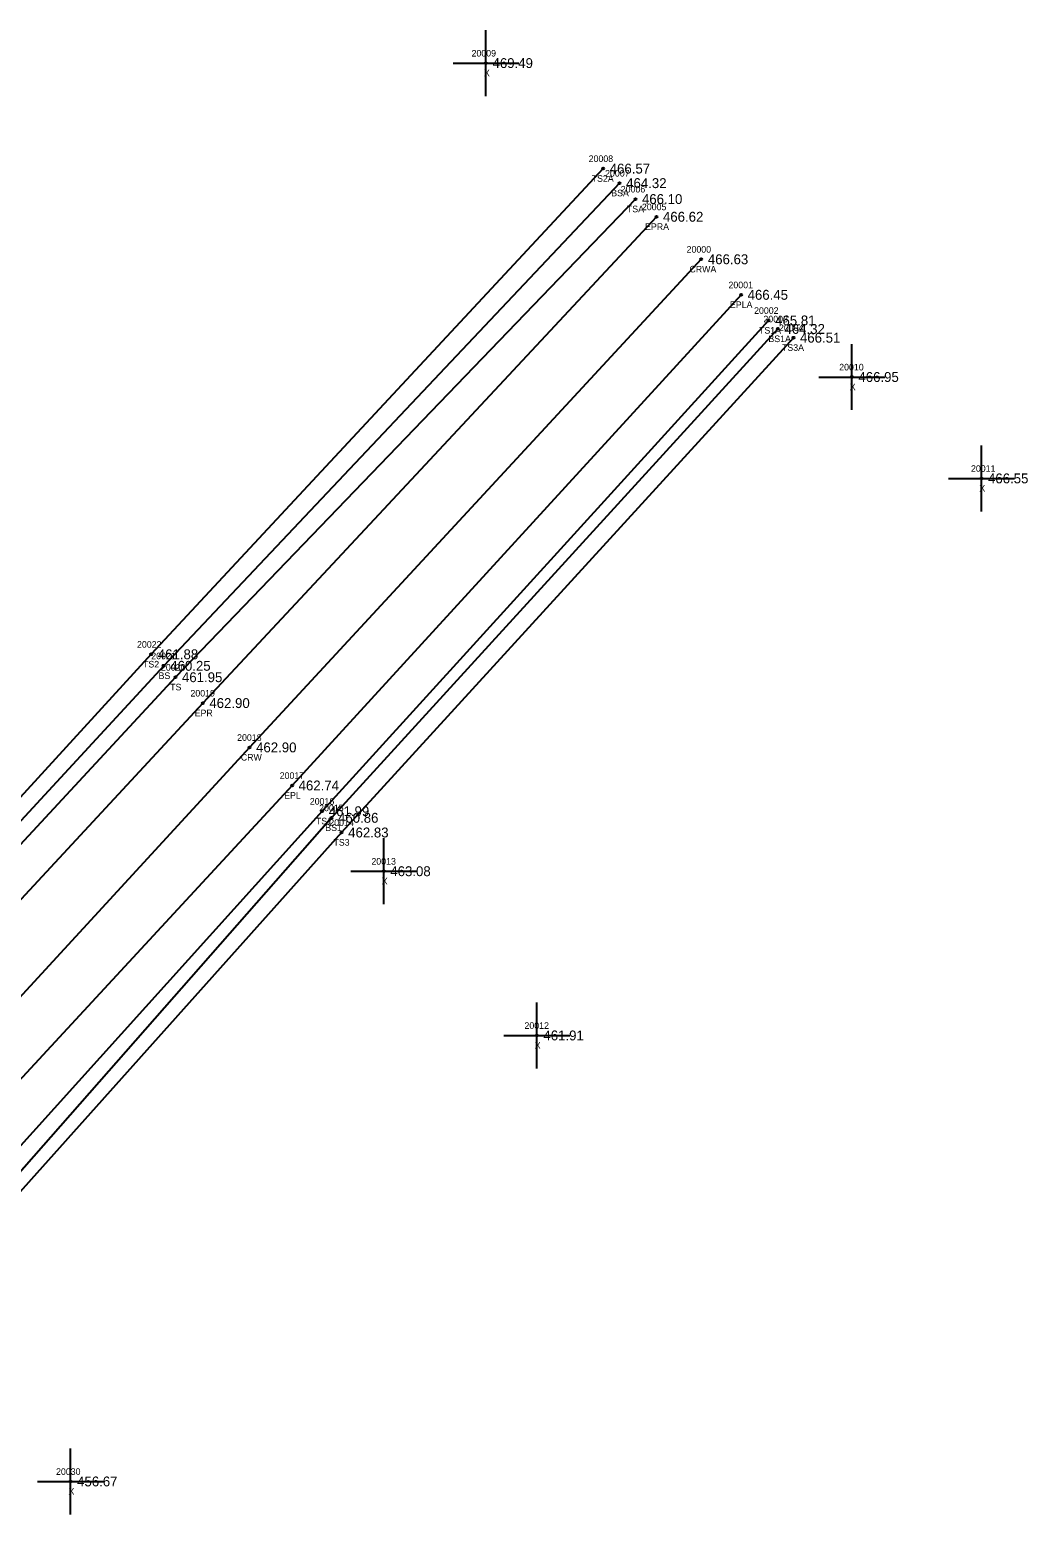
# Model space of a CAD drawing. Extents: x 1763022 to 1764007, y 824123 to 825394.
# Drawn here: x 1763855.9 to 1764007.5, y 825164.8 to 825393.8 of the extents above; entities that cross this region are included whole.
import ezdxf

# ---------------------------------------------------------------- set-up
doc = ezdxf.new("R2010")
doc.units = 0
for name, color, linetype in [('RD_DTM_BkLn1', 7, 'Continuous'), ('RD_DTM_BkLn2', 7, 'Continuous'), ('RD_DTM_BkLn_txCode', 7, 'Continuous'), ('RD_EX_Misc', 7, 'Continuous'), ('RD_EX_Misc_txCode', 7, 'Continuous'), ('RD_EX_Road', 7, 'Continuous'), ('RD_EX_Road_txCode', 7, 'Continuous'), ('RD_EX_TX_Misc_ELEV', 7, 'Continuous'), ('RD_EX_TX_Road_ELEV', 7, 'Continuous'), ('RD_HC_Survey_ELEV', 7, 'Continuous'), ('RD_HC_Survey_txCode', 7, 'Continuous'), ('RD_SMD_Locator', 7, 'Continuous')]:
    doc.layers.add(name, color=color, linetype=linetype)

msp = doc.modelspace()

# ---------------------------------------------------------------- linework, layer by layer
at = {"layer": 'RD_DTM_BkLn1'}
msp.add_lwpolyline([(1763957.85, 825358.99), (1763889.22, 825284.86), (1763820.79, 825210.5), (1763751.37, 825137.44), (1763682.52, 825063.34), (1763613.99, 824989.62), (1763581.46, 824952.08), (1763550.2, 824912.66), (1763519.29, 824872.78), (1763491.16, 824832.15)], dxfattribs=at)
at = {"layer": 'RD_DTM_BkLn2'}
for points in [[(1763945.44, 825370.55), (1763876.18, 825297.25), (1763807.34, 825222.7), (1763776.17, 825191.55), (1763769.13, 825184.38), (1763768.64, 825186.89), (1763767.13, 825189.37), (1763755.67, 825200.47), (1763739.73, 825215.82)], [(1763942.94, 825372.76), (1763874.29, 825299), (1763805.88, 825224.24), (1763774.23, 825192.97), (1763772.12, 825191.31), (1763767.89, 825192.87), (1763756.18, 825201.61), (1763741.69, 825218.79)], [(1763947.84, 825368.13), (1763877.96, 825295.52), (1763808.96, 825221.13), (1763778.03, 825189.45), (1763771.43, 825183.03), (1763768.35, 825183.44), (1763766.15, 825186.32), (1763754.14, 825199.28), (1763738.29, 825214.7)], [(1763968.07, 825349.7), (1763900.27, 825275.17), (1763832.66, 825200.26), (1763762.42, 825126.65), (1763692.83, 825054.38), (1763655.96, 825013.92), (1763657.67, 825011.86), (1763660.66, 825010.25)], [(1763969.49, 825348.41), (1763901.67, 825274.17), (1763835.08, 825198.5), (1763765.09, 825125.58), (1763695.51, 825052.15), (1763658.81, 825013.59)], [(1763971.84, 825347.08), (1763903.21, 825271.94), (1763836.32, 825197.24), (1763767.44, 825123.48), (1763698.39, 825048.89), (1763660.66, 825010.25)]]:
    msp.add_lwpolyline(points, dxfattribs=at)
at = {"layer": 'RD_EX_Misc'}
for p, q in [((1763925.14, 825383.78), (1763925.14, 825393.78)), ((1763920.14, 825388.78), (1763930.14, 825388.78)), ((1763980.72, 825336.11), (1763980.72, 825346.11)), ((1763975.72, 825341.11), (1763985.72, 825341.11)), ((1764000.41, 825320.71), (1764000.41, 825330.71)), ((1763995.41, 825325.71), (1764005.41, 825325.71)), ((1763909.61, 825261.06), (1763909.61, 825271.06)), ((1763904.61, 825266.06), (1763914.61, 825266.06)), ((1763932.87, 825236.12), (1763932.87, 825246.12)), ((1763927.87, 825241.12), (1763937.87, 825241.12)), ((1763862.03, 825168.39), (1763862.03, 825178.39)), ((1763857.03, 825173.39), (1763867.03, 825173.39))]:
    msp.add_line(p, q, dxfattribs=at)
at = {"layer": 'RD_EX_Road'}
for points in [[(1763951.03, 825365.44), (1763882.12, 825291.59), (1763813.3, 825217.44), (1763784.22, 825184.64), (1763754.38, 825152.48), (1763744.67, 825142.84), (1763675.27, 825070.17), (1763607.46, 824995.53), (1763574.27, 824958.09), (1763542.37, 824919.2), (1763512.11, 824877.96), (1763483.2, 824837.35)], [(1763963.89, 825353.59), (1763895.68, 825279.08), (1763827.34, 825205.22), (1763758.38, 825131.33), (1763689.43, 825057.33), (1763653.53, 825018.75), (1763637.74, 825000.8), (1763620.71, 824983.81), (1763588.78, 824946.6), (1763557.13, 824907.38), (1763526.52, 824867.67), (1763498.43, 824827.25)]]:
    msp.add_lwpolyline(points, dxfattribs=at)
at = {"layer": 'RD_SMD_Locator'}
for centre in [(1763925.14, 825388.78), (1763942.94, 825372.76), (1763945.44, 825370.55), (1763947.84, 825368.13), (1763951.03, 825365.44), (1763957.85, 825358.99), (1763963.89, 825353.59), (1763968.07, 825349.7), (1763969.49, 825348.41), (1763971.84, 825347.08), (1763980.72, 825341.11), (1764000.41, 825325.71), (1763874.29, 825299), (1763876.18, 825297.25), (1763877.96, 825295.52), (1763882.12, 825291.59), (1763889.22, 825284.86), (1763895.68, 825279.08), (1763900.27, 825275.17), (1763901.67, 825274.17), (1763903.21, 825271.94), (1763909.61, 825266.06), (1763932.87, 825241.12), (1763862.03, 825173.39)]:
    msp.add_circle(centre, 0.15, dxfattribs=at)

# ---------------------------------------------------------------- texts
at = {"layer": 'RD_DTM_BkLn_txCode'}
for s, p in [('20008', (1763940.74, 825373.76)), ('TS2A', (1763941.2, 825370.76)), ('20007', (1763943.24, 825371.55)), ('BSA', (1763944.17, 825368.55)), ('20006', (1763945.62, 825369.13)), ('TSA', (1763946.55, 825366.13)), ('20002', (1763965.87, 825350.7)), ('20003', (1763967.29, 825349.41)), ('TS1A', (1763966.62, 825347.7)), ('20004', (1763969.65, 825348.08)), ('BS1A', (1763968.05, 825346.41)), ('TS3A', (1763970.11, 825345.08)), ('20022', (1763872.13, 825300)), ('TS2', (1763873.04, 825297)), ('20021', (1763874.3, 825298.25)), ('20020', (1763875.76, 825296.52)), ('BS', (1763875.4, 825295.25)), ('TS', (1763877.16, 825293.52)), ('20016', (1763898.38, 825276.17)), ('20015', (1763899.8, 825275.17)), ('TS1', (1763899.31, 825273.17)), ('BS1', (1763900.73, 825272.17)), ('20014', (1763901.34, 825272.94)), ('TS3', (1763901.97, 825269.94))]:
    msp.add_text(s, height=1, dxfattribs=at).set_placement(p)
at = {"layer": 'RD_EX_Misc_txCode'}
for s, p in [('20009', (1763922.95, 825389.78)), ('X', (1763924.83, 825386.78)), ('20010', (1763978.8, 825342.11)), ('X', (1763980.4, 825339.11)), ('20011', (1763998.82, 825326.71)), ('X', (1764000.09, 825323.71)), ('20013', (1763907.74, 825267.06)), ('X', (1763909.3, 825264.06)), ('20012', (1763930.99, 825242.12)), ('X', (1763932.55, 825239.12)), ('20030', (1763859.83, 825174.39)), ('X', (1763861.72, 825171.39))]:
    msp.add_text(s, height=1, dxfattribs=at).set_placement(p)
at = {"layer": 'RD_EX_Road_txCode'}
for s, p in [('20005', (1763948.83, 825366.44)), ('EPRA', (1763949.31, 825363.44)), ('20001', (1763961.98, 825354.59)), ('EPLA', (1763962.2, 825351.59)), ('20019', (1763880.25, 825292.59)), ('EPR', (1763880.89, 825289.59)), ('20017', (1763893.81, 825280.08)), ('EPL', (1763894.48, 825277.08))]:
    msp.add_text(s, height=1, dxfattribs=at).set_placement(p)
at = {"layer": 'RD_EX_TX_Misc_ELEV'}
for s, p in [('469.49', (1763926.14, 825388.03)), ('466.57', (1763943.94, 825372.01)), ('464.32', (1763946.44, 825369.8)), ('466.10', (1763948.84, 825367.38)), ('465.81', (1763969.07, 825348.95)), ('464.32', (1763970.49, 825347.66)), ('466.51', (1763972.84, 825346.33)), ('466.95', (1763981.72, 825340.36)), ('466.55', (1764001.41, 825324.96)), ('461.88', (1763875.29, 825298.25)), ('460.25', (1763877.18, 825296.5)), ('461.95', (1763878.96, 825294.77)), ('461.99', (1763901.27, 825274.42)), ('460.86', (1763902.67, 825273.42)), ('462.83', (1763904.21, 825271.19)), ('463.08', (1763910.61, 825265.31)), ('461.91', (1763933.87, 825240.37)), ('456.67', (1763863.03, 825172.64))]:
    msp.add_text(s, height=1.5, dxfattribs=at).set_placement(p)
at = {"layer": 'RD_EX_TX_Road_ELEV'}
for s, p in [('466.62', (1763952.03, 825364.69)), ('466.45', (1763964.89, 825352.84)), ('462.90', (1763883.12, 825290.84)), ('462.74', (1763896.68, 825278.33))]:
    msp.add_text(s, height=1.5, dxfattribs=at).set_placement(p)
at = {"layer": 'RD_HC_Survey_ELEV'}
for s, p in [('466.63', (1763958.85, 825358.24)), ('462.90', (1763890.22, 825284.11))]:
    msp.add_text(s, height=1.5, dxfattribs=at).set_placement(p)
at = {"layer": 'RD_HC_Survey_txCode'}
for s, p in [('20000', (1763955.62, 825359.99)), ('CRWA', (1763956.05, 825356.99)), ('20018', (1763887.34, 825285.86)), ('CRW', (1763887.9, 825282.86))]:
    msp.add_text(s, height=1, dxfattribs=at).set_placement(p)

doc.saveas('drawing.dxf')
